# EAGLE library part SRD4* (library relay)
Safety Relay SCHRACK 4 pole 8 A Source: http://www.schrack.com/.. 6685.pdf
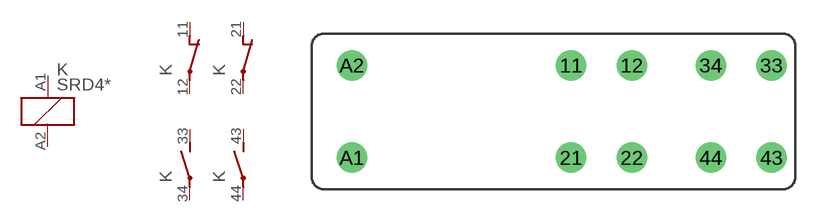
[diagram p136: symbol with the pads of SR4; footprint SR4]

Designator prefix K; gates 1=K 2=O 3=O 4=S 5=S

## SRD4005 (OC_FARNELL: unknown; OC_NEWARK: unknown), SRD4006 (OC_FARNELL: unknown; OC_NEWARK: unknown), SRD4009 (OC_FARNELL: unknown; OC_NEWARK: unknown), SRD4012 (OC_FARNELL: unknown; OC_NEWARK: unknown), SRD4015 (OC_FARNELL: unknown; OC_NEWARK: unknown), SRD4018 (OC_FARNELL: unknown; OC_NEWARK: unknown), SRD4021 (OC_FARNELL: unknown; OC_NEWARK: unknown), SRD4024 (OC_FARNELL: unknown; OC_NEWARK: unknown), SRD4036 (OC_FARNELL: unknown; OC_NEWARK: unknown), SRD4040 (OC_FARNELL: unknown; OC_NEWARK: unknown), SRD4048 (OC_FARNELL: unknown; OC_NEWARK: unknown), SRD4060 (OC_FARNELL: unknown; OC_NEWARK: unknown), SRD4085 (OC_FARNELL: unknown; OC_NEWARK: unknown), SRD4110 (OC_FARNELL: unknown; OC_NEWARK: unknown)  [SR4]
11  2:O  pas
12  2:P  pas
21  3:O  pas
22  3:P  pas
33  4:S  pas
34  4:P  pas
43  5:S  pas
44  5:P  pas
A1  1:1  pas
A2  1:2  pas

## Footprint SR4 (pad centres in mm)
Safety Relay SCHRACK 4 pole 8 A Source: http://www.schrack.com/.. 6685.pdf
drill 1.3 pad 2.5 round: 11 0,3.8; 12 5,3.8; 21 0,-3.8; 22 5,-3.8; 33 16.5,3.8; 34 11.5,3.8; 43 16.5,-3.8; 44 11.5,-3.8; A1 -18.05,-3.8; A2 -18.05,3.8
